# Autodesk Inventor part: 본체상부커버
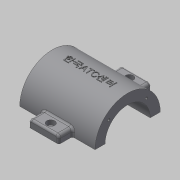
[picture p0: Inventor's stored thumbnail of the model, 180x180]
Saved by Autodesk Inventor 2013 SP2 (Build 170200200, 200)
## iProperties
Created: 2015-12
Part Number: 본체상부커버
Material: 일반
Document SubType Name: Modeling
Designer: mduedu
Density: 1 g/cm^3
Author: mduedu
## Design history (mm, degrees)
sketch "스케치1"
  geometry: L1 (45, 40)-(-45, 40); L2 (-45, 40)-(-45, -40); L3 (-45, -40)-(45, -40); L4 (45, -40)-(45, 40); L5 (45, 40)-(-45, -40); L6 (-45, 40)-(45, -40); 2 further points
  constraints: 12 end point, 2 midpoint, 2 parallel, 1 coincident, 1 horizontal, 1 perpendicular, 3 other
  dimensions: "d0" = 90 distance of L2.end L3.end; "d2" = 80 distance of L1.end L2.end
extrude "돌출1" new body sketch "스케치1" distance "d3" = 10; taper "d4" = 0 deg
sketch "스케치2"
  geometry: C1 r 32.5 at (80, 0); 1 further point
  constraints: 1 centre point
  dimensions: "d5" = 65 diameter of C1; "d116" = 80 distance of point (0, 0) C1.centre
extrude "돌출2" join sketch "스케치2" stored distance "d7" = 75; taper "d8" = 0 deg
sketch "스케치3"
  geometry: L1 (-27.5, -20)-(27.5, -20); L2 (27.5, -20)-(27.5, 20); L3 (27.5, 20)-(-27.5, 20); L4 (-27.5, 20)-(-27.5, -20); L5 (-27.5, -20)-(27.5, 20); L6 (27.5, -20)-(-27.5, 20); 1 further point
  constraints: 12 end point, 2 midpoint, 2 parallel, 1 horizontal, 1 perpendicular
  dimensions: "d9" = 55 distance of L2.end L3.end; "d11" = 40 distance of L1.end L2.end
extrude "돌출3" new body sketch "스케치3" stored distance "d12" = 75; taper "d13" = 0 deg
fillet "모깎기1"
fillet "모깎기2"
feature "결합1"
  node "솔리드2"
sketch "스케치4"
  geometry: L1 (-37.5, 47.5)-(37.5, 47.5) reference; L2 (32.5, 47.5)-(40.208, 10); L3 (37.5, 47.5)-(37.5, 112.5) reference; L4 (60.208, 0)-(60.208, 10) reference; L5 (60.208, 10)-(-60.208, 10) reference; 1 further point
  constraints: 2 end point, 2 point on line
  dimensions: "d15" = 5 distance from line of L2.start L3; "d117" = 20 distance from line of L2.end L4
sketch "스케치5"
  geometry: L1 (10, 35.208)-(56.729, 22.687); L2 (0, 60.208)-(10, 60.208) reference; L3 (10, -60.208)-(10, 60.208) reference; 2 further points
  constraints: 2 end point, 1 point on line, 2 other
  dimensions: "d118" = 25 distance from line of L1.start L2; "d119" = 75 deg angle of L1 L3
feature "리브1" dims "d19" = 1, "d20" = 6, "d21" = 0, "d22" = 0, "d23" = 1, "d24" = 1
feature "리브2" dims "d25" = 1, "d26" = 6, "d27" = 0, "d28" = 0, "d29" = 1, "d30" = 1
fillet "모깎기4" dims "d31" = 2
fillet "모깎기5" dims "d32" = 2
fillet "모깎기6" dims "d33" = 2
sketch "스케치6"
  geometry: L1 (0, 0)-(-32.88, 32.88); L2 (0, 0)-(-46.5, 0); A1 r 46.5 centre (0, 0) between (-32.88, 32.88) and (-46.5, 0); 5 further points
  constraints: 4 end point, 2 coincident, 2 point on circle, 1 centre point, 1 horizontal, 5 other
  dimensions: "d120" = 93 diameter of A1; "d122" = 45 deg angle of L1 L2; "d126" = 360 deg dimension on point (0, 0) point (-32.88, 32.88) (derived)
hole "구멍1" sketch "스케치6" at (-32.88, 32.88), (-32.88, -32.88), (32.88, -32.88), (32.88, 32.88) diameter "d34" = 7; stored, may be unused: countersink angle "d38" = 90 deg, drill point angle "d40" = 118 deg; dims "d35" = 6, "d36" = 12, "d37" = 3, "d39" = 8
fillet "모깎기13" dims "d131" = 3
hole "구멍2" diameter "d44" = 45; stored, may be unused: countersink angle "d48" = 90 deg, drill point angle "d50" = 118 deg; dims "d42" = 10, "d43" = 10, "d45" = 6, "d46" = 4, "d47" = 2, "d49" = 8
sketch "스케치7" dims "d52" = 26.5
  geometry: L1 (0, 0)-(32.5, 0); L2 (0, 0)-(22.981, 22.981); A1 r 32.5 centre (0, 0) between (32.5, 0) and (22.981, 22.981) reference; 3 further points
  constraints: 4 end point, 2 point on circle, 1 coincident, 1 horizontal, 1 point on line, 3 other
  dimensions: "d51" = 45 deg angle of L2 L1
hole "구멍3" sketch "스케치7" at (18.738, 18.738) diameter "d54" = 2.459; stored, may be unused: countersink angle "d58" = 90 deg, drill point angle "d60" = 118 deg; dims "d55" = 8, "d56" = 4, "d57" = 2, "d59" = 10
sketch "스케치8"
  geometry: L1 (72.5, 31.623)-(72.5, 46); L2 (72.5, 46)-(87.5, 46); L3 (87.5, 46)-(87.5, 31.623); A1 r 32.5 centre (80, 0) between (87.5, 31.623) and (72.5, 31.623) reference; 2 further points
  constraints: 6 end point, 2 point on circle, 1 horizontal, 1 midpoint, 1 parallel, 1 vertical, 1 vertical alignment
  dimensions: "d64" = 15 distance of L1.end L2.end; "d66" = 46 distance from line of L2 A1.centre
extrude "돌출4" join sketch "스케치8" stored distance "d67" = 30; taper "d68" = 0 deg
fillet "모깎기8" dims "d69" = 3
fillet "모깎기9" dims "d70" = 2
node "작업 평면2"
sketch "스케치16"
  geometry: L1 (33.166, 72.5)-(44, 72.5) reference; L2 (42.5, 72.5)-(28.53, 64.434); L3 (46, 75.5)-(46, 84.5) reference; 2 further points
  constraints: 2 end point, 1 point on line, 2 other
  dimensions: "d138" = 30 deg angle of L2 L1; "d139" = 3.5 distance from line of L2.start L3
feature "리브3" sketch "스케치16" dims "d140" = 1, "d141" = 3, "d142" = 0, "d143" = 0, "d144" = 1, "d145" = 1
fillet "모깎기14" dims "d146" = 1
fillet "모깎기15" dims "d147" = 1
sketch "스케치9"
  geometry: L1 (-76, -110)-(76, -110); L2 (76, -110)-(76, 0); L3 (76, 0)-(-76, 0); L4 (-76, 0)-(-76, -110); L5 (-46, 4.5)-(-46, -4.5) reference; L6 (-60.208, -80)-(60.208, -80) reference; C1 r 32.5 at (0, 0) reference; 2 further points
  constraints: 8 end point, 2 parallel, 1 coincident, 1 horizontal, 1 midpoint, 1 perpendicular
  dimensions: "d72" = 30 distance between parallel lines of L4 L5; "d148" = 30 distance between parallel lines of L6 L1
extrude "돌출5" cut sketch "스케치9" stored distance "d73" = 0; taper "d74" = 0 deg
node "작업 평면3"
sketch "스케치17"
  geometry: 2 further points
  constraints: 1 coincident, 1 other
feature "엠보싱1" sketch "스케치17" dims "d12" = 75, "d13" = 0, "d150" = 0.5, "d151" = 0
sketch "스케치18"
  geometry: L1 (-3, -1.039)-(-3, -10.834) reference; L2 (27, -10.834)-(27, -1.039) reference; L3 (0, -12.834)-(24, -12.834) reference; L4 (-3, -5.936)-(27, -5.936); L5 (12, -12.834)-(12, 33.166); 1 further point
  constraints: 4 end point, 4 midpoint, 1 perpendicular, 1 point on line
hole "구멍8" sketch "스케치18" at (12, -5.936) diameter "d152" = 4.5; stored, may be unused: countersink angle "d156" = 90 deg, drill point angle "d158" = 118 deg; dims "d153" = 6, "d154" = 8, "d155" = 4.6, "d157" = 8
node "솔리드1"
mirror "대칭1"
mirror "대칭2"
pattern_circular "원형 패턴1" dims angle "d62" = 360 deg
mirror "대칭3"
mirror "대칭7"
mirror "대칭4"
mirror "대칭8"
other parameters: "d137" = -5
